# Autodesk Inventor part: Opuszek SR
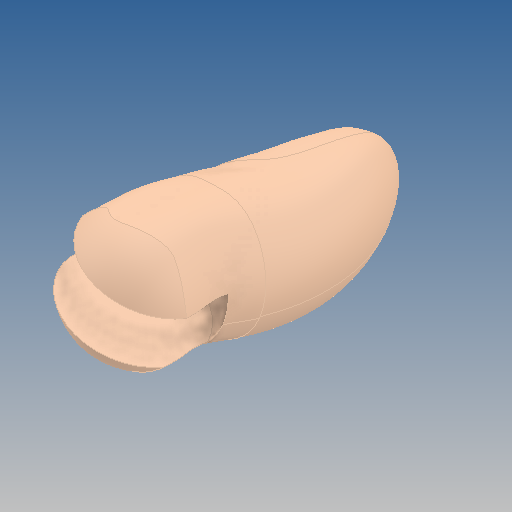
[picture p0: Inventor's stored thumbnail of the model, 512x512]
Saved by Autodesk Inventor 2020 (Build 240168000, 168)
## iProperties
Created: 2019-10
Part Number: Opuszek SR
Material: GFRP
Document SubType Name: Modeling
Designer: yello
Density: 1.75 g/cm^3
Appearance: Default
Author: yello
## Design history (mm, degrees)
feature "Opuszek SR"
body "Solid1"
